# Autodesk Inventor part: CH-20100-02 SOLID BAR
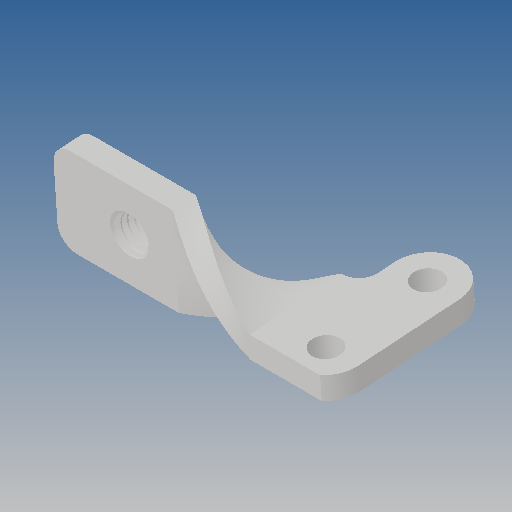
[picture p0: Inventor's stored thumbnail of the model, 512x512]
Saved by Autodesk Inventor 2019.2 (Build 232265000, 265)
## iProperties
Created: 2012-09
Part Number: CH-20100-02 SOLID BAR
Material: Ogólny
Document SubType Name: Modeling
Designer: CADENGINEERING4
Density: 1 g/cm^3
Appearance: Domyślna
Author: CADENGINEERING4
Revision Number: ÈÎºÎ
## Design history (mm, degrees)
feature "ÇÐ³ý-É¨Ãè1"
node "Bryła1"
